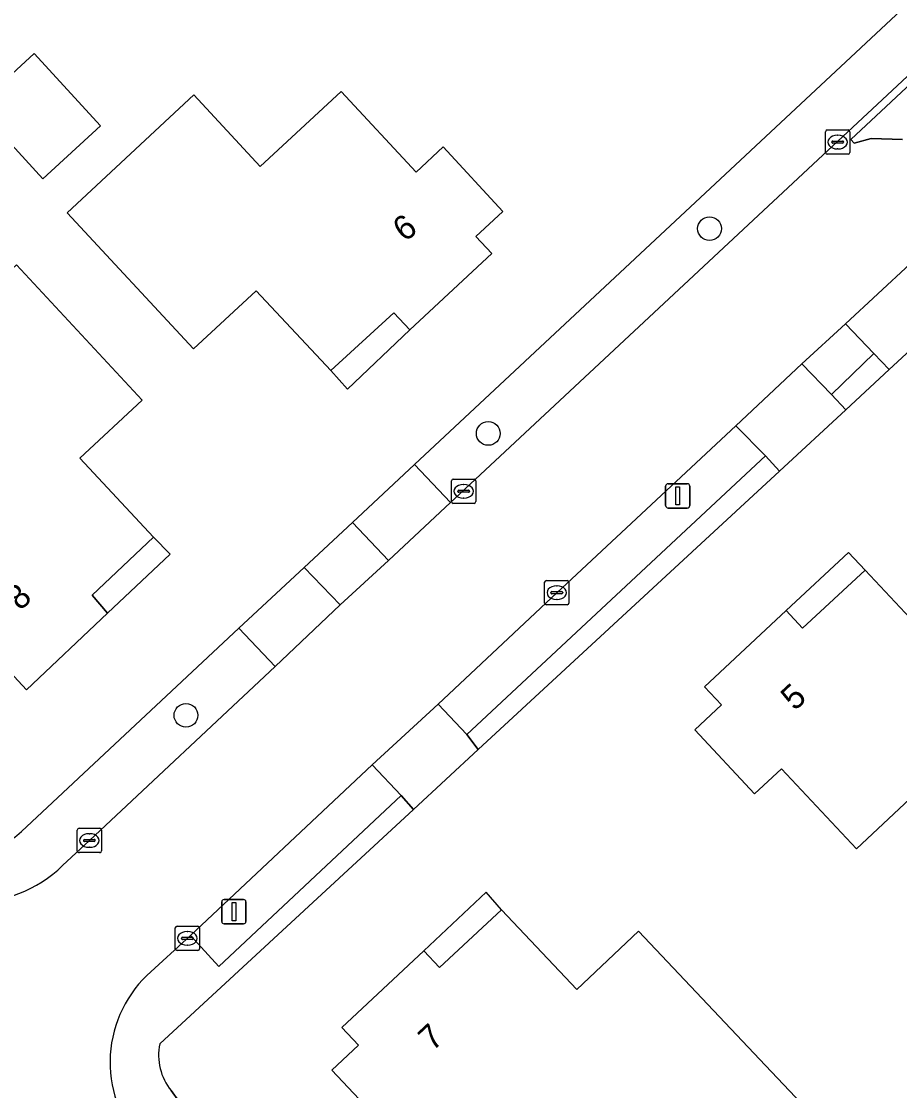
# Model space of a CAD drawing. Extents: x 162661 to 163484, y 380247 to 381230.
# Drawn here: x 163330.1 to 163366.19, y 380849.27 to 380893.22 of the extents above; entities that cross this region are included whole.
import ezdxf

# ---------------------------------------------------------------- set-up
doc = ezdxf.new("R2010")
doc.units = 0
for name, color, linetype in [('IMGEO_Berm_groen', 7, 'Continuous'), ('IMGEO_Boom', 7, 'Continuous'), ('IMGEO_Erf', 7, 'Continuous'), ('IMGEO_Groenvoorziening', 7, 'Continuous'), ('IMGEO_Haag', 7, 'Continuous'), ('IMGEO_Kolk', 7, 'Continuous'), ('IMGEO_Lichtmast', 7, 'Continuous'), ('IMGEO_Pand', 7, 'Continuous'), ('IMGEO_Pand_nummerreeks', 7, 'Continuous'), ('IMGEO_Pand_overbouw', 7, 'Continuous'), ('IMGEO_Parkeervlak_halfverhard', 7, 'Continuous'), ('IMGEO_Rijbaan_lokaal_gesloten', 7, 'Continuous'), ('IMGEO_Voetpad_halfverhard', 7, 'Continuous'), ('IMGEO_Voetpad_open', 7, 'Continuous')]:
    doc.layers.add(name, color=color, linetype=linetype)

msp = doc.modelspace()

# ---------------------------------------------------------------- linework, layer by layer
at = {"layer": 'IMGEO_Berm_groen'}
for points in [[(163340.526, 380866.706), (163339.041, 380868.279), (163330.099, 380859.929)], [(163331.793, 380858.522), (163332.894, 380859.553), (163340.526, 380866.706)]]:
    msp.add_lwpolyline(points, dxfattribs=at)
for centre, radius, start, end in [((163327.945, 380862.085), 3.048, 239.5806, 314.9707), ((163328.001, 380862.453), 5.462, 223.9538, 313.9694)]:
    msp.add_arc(centre, radius, start, end, dxfattribs=at)
at = {"layer": 'IMGEO_Boom'}
for centre in [(163358.382, 380884.702), (163349.288, 380876.285), (163336.864, 380864.698)]:
    msp.add_circle(centre, 0.489, dxfattribs=at)
at = {"layer": 'IMGEO_Erf'}
for points in [[(163412.189, 380922.438), (163401.222, 380911.928), (163398.601, 380909.502), (163391.052, 380902.669), (163388.46, 380900.109), (163368.391, 380881.338), (163365.767, 380878.911), (163363.981, 380877.26), (163361.251, 380874.736), (163348.876, 380863.295), (163346.208, 380860.828), (163335.787, 380851.194)], [(163330.099, 380859.929), (163339.041, 380868.279), (163341.718, 380870.779), (163343.701, 380872.63), (163346.254, 380875.013), (163369.133, 380896.376), (163371.715, 380898.787), (163373.061, 380900.044), (163376.845, 380903.636), (163390.208, 380916.036)], [(163336.256, 380849.272), (163336.881, 380848.403), (163338.801, 380846.249), (163364.11, 380819.217)]]:
    msp.add_lwpolyline(points, dxfattribs=at)
for points in [[(163333.348, 380888.927), (163330.977, 380886.75), (163328.248, 380889.724), (163330.619, 380891.9)], [(163346.319, 380887.029), (163347.431, 380888.061), (163349.892, 380885.413), (163348.781, 380884.381), (163349.434, 380883.679), (163346.063, 380880.54), (163345.41, 380881.242), (163342.822, 380878.871), (163339.742, 380882.153), (163337.167, 380879.761), (163331.974, 380885.353), (163337.191, 380890.199), (163339.918, 380887.263), (163343.236, 380890.346)], [(163335.526, 380872.02), (163333.012, 380869.643), (163333.644, 380868.901), (163330.314, 380865.749), (163329.63, 380866.48), (163328.538, 380865.451), (163326.089, 380868.083), (163327.193, 380869.11), (163324.125, 380872.407), (163327.423, 380875.474), (163324.709, 380878.39), (163329.893, 380883.212), (163335.061, 380877.654), (163332.502, 380875.273)], [(163370.437, 380859.384), (163367.707, 380862.295), (163364.418, 380859.211), (163361.334, 380862.5), (163360.233, 380861.468), (163357.771, 380864.095), (163358.873, 380865.128), (163358.173, 380865.876), (163361.528, 380869), (163362.208, 380868.274), (163364.776, 380870.664), (163367.855, 380867.382), (163370.408, 380869.776), (163375.607, 380864.234)], [(163363.882, 380846.918), (163359.74, 380843.055), (163356.584, 380846.44), (163355.528, 380845.443), (163352.791, 380848.343), (163349.513, 380845.249), (163346.419, 380848.527), (163345.322, 380847.491), (163342.852, 380850.109), (163343.953, 380851.135), (163343.269, 380851.862), (163346.634, 380855.024), (163347.281, 380854.326), (163349.833, 380856.699), (163352.921, 380853.428), (163355.466, 380855.831), (163360.682, 380850.307)]]:
    msp.add_lwpolyline(points, close=True, dxfattribs=at)
for centre, radius, start, end in [((163327.945, 380862.085), 3.048, 239.5806, 314.9707), ((163338.036, 380850.725), 2.297, 168.2096, 219.2166)]:
    msp.add_arc(centre, radius, start, end, dxfattribs=at)
at = {"layer": 'IMGEO_Groenvoorziening'}
for points in [[(163369.133, 380896.376), (163346.254, 380875.013), (163347.737, 380873.443), (163370.584, 380894.778)], [(163363.39, 380877.885), (163363.981, 380877.26), (163365.767, 380878.911), (163365.131, 380879.565)], [(163360.677, 380875.363), (163348.4, 380863.91), (163348.876, 380863.295), (163361.251, 380874.736)], [(163343.204, 380869.236), (163345.186, 380871.061), (163343.701, 380872.63), (163341.718, 380870.779)]]:
    msp.add_lwpolyline(points, close=True, dxfattribs=at)
for points in [[(163369.075, 380891.078), (163369.074, 380892.193), (163369.322, 380892.879), (163369.165, 380893.006), (163364.183, 380888.363), (163364.325, 380888.214), (163365.021, 380888.414), (163366.314, 380888.368)], [(163335.787, 380851.194), (163346.208, 380860.828), (163345.701, 380861.401), (163338.217, 380854.377), (163337.045, 380855.644), (163335.253, 380854.006)], [(163364.11, 380819.217), (163338.801, 380846.249), (163336.881, 380848.403), (163336.256, 380849.272)]]:
    msp.add_lwpolyline(points, dxfattribs=at)
for centre, radius, start, end in [((163338.712, 380850.437), 4.97, 134.1, 224.5357), ((163338.036, 380850.725), 2.297, 168.2096, 219.2166)]:
    msp.add_arc(centre, radius, start, end, dxfattribs=at)
at = {"layer": 'IMGEO_Haag'}
for points in [[(163363.39, 380877.885), (163363.981, 380877.26), (163365.767, 380878.911), (163365.131, 380879.565)], [(163360.677, 380875.363), (163348.4, 380863.91), (163348.876, 380863.295), (163361.251, 380874.736)]]:
    msp.add_lwpolyline(points, close=True, dxfattribs=at)
at = {"layer": 'IMGEO_Kolk'}
for p, q in [((163363.221, 380888.759), (163364.073, 380888.759)), ((163363.146, 380887.833), (163363.146, 380888.685)), ((163363.448, 380888.302), (163363.846, 380888.302)), ((163363.634, 380888.539), (163363.659, 380888.539)), ((163364.147, 380888.685), (163364.147, 380887.833)), ((163363.405, 380888.253), (163363.405, 380888.265)), ((163363.843, 380888.216), (163363.445, 380888.216)), ((163363.657, 380887.979), (163363.632, 380887.979)), ((163363.889, 380888.265), (163363.889, 380888.253)), ((163364.073, 380887.759), (163363.221, 380887.759)), ((163347.775, 380873.482), (163347.775, 380874.334)), ((163347.85, 380874.408), (163348.702, 380874.408)), ((163348.776, 380874.334), (163348.776, 380873.482)), ((163348.034, 380873.902), (163348.034, 380873.914)), ((163348.472, 380873.865), (163348.074, 380873.865)), ((163348.077, 380873.951), (163348.475, 380873.951)), ((163348.263, 380874.188), (163348.288, 380874.188)), ((163348.518, 380873.914), (163348.518, 380873.902)), ((163348.702, 380873.408), (163347.85, 380873.408)), ((163348.286, 380873.628), (163348.261, 380873.628)), ((163351.603, 380869.313), (163351.603, 380870.165)), ((163351.678, 380870.239), (163352.53, 380870.239)), ((163352.091, 380870.019), (163352.116, 380870.019)), ((163352.604, 380870.165), (163352.604, 380869.313)), ((163351.862, 380869.733), (163351.862, 380869.745)), ((163352.3, 380869.696), (163351.902, 380869.696)), ((163351.905, 380869.782), (163352.303, 380869.782)), ((163352.114, 380869.459), (163352.089, 380869.459)), ((163352.346, 380869.745), (163352.346, 380869.733)), ((163352.53, 380869.239), (163351.678, 380869.239)), ((163332.393, 380859.127), (163332.393, 380859.979)), ((163332.468, 380860.053), (163333.32, 380860.053)), ((163332.881, 380859.833), (163332.906, 380859.833)), ((163333.394, 380859.979), (163333.394, 380859.127)), ((163332.652, 380859.547), (163332.652, 380859.559)), ((163333.09, 380859.51), (163332.692, 380859.51)), ((163332.695, 380859.596), (163333.093, 380859.596)), ((163332.904, 380859.273), (163332.879, 380859.273)), ((163333.136, 380859.559), (163333.136, 380859.547)), ((163333.32, 380859.053), (163332.468, 380859.053)), ((163336.421, 380855.105), (163336.421, 380855.957)), ((163336.496, 380856.031), (163337.348, 380856.031)), ((163336.909, 380855.811), (163336.934, 380855.811)), ((163337.422, 380855.957), (163337.422, 380855.105)), ((163336.68, 380855.525), (163336.68, 380855.537)), ((163337.118, 380855.488), (163336.72, 380855.488)), ((163336.723, 380855.574), (163337.121, 380855.574)), ((163337.164, 380855.537), (163337.164, 380855.525)), ((163337.348, 380855.031), (163336.496, 380855.031)), ((163336.932, 380855.251), (163336.907, 380855.251))]:
    msp.add_line(p, q, dxfattribs=at)
for points in [[(163363.221, 380888.759), (163364.073, 380888.759)], [(163363.146, 380887.833), (163363.146, 380888.685)], [(163364.147, 380888.685), (163364.147, 380887.833)], [(163364.073, 380887.759), (163363.221, 380887.759)], [(163347.775, 380873.482), (163347.775, 380874.334)], [(163347.85, 380874.408), (163348.702, 380874.408)], [(163348.776, 380874.334), (163348.776, 380873.482)], [(163348.702, 380873.408), (163347.85, 380873.408)], [(163351.603, 380869.313), (163351.603, 380870.165)], [(163351.678, 380870.239), (163352.53, 380870.239)], [(163352.604, 380870.165), (163352.604, 380869.313)], [(163352.53, 380869.239), (163351.678, 380869.239)], [(163332.393, 380859.127), (163332.393, 380859.979)], [(163332.468, 380860.053), (163333.32, 380860.053)], [(163333.394, 380859.979), (163333.394, 380859.127)], [(163333.32, 380859.053), (163332.468, 380859.053)], [(163336.421, 380855.105), (163336.421, 380855.957)], [(163336.496, 380856.031), (163337.348, 380856.031)], [(163337.422, 380855.957), (163337.422, 380855.105)], [(163337.348, 380855.031), (163336.496, 380855.031)]]:
    msp.add_lwpolyline(points, dxfattribs=at)
for centre, radius, start, end in [((163363.223, 380888.683), 0.0765, 91.552, 178.448), ((163363.223, 380888.683), 0.0765, 91.552, 178.448), ((163364.071, 380888.683), 0.0765, 1.552, 88.448), ((163364.071, 380888.683), 0.0765, 1.552, 88.448), ((163363.445, 380888.262), 0.0403, 85.8775, 175.7526), ((163363.85, 380888.264), 0.0386, 1.7309, 96.639), ((163363.442, 380888.252), 0.0366, 178.938, 274.7102), ((163363.846, 380888.259), 0.043, 264.8664, 352.4533), ((163363.223, 380887.835), 0.0765, 181.552, 268.448), ((163363.223, 380887.835), 0.0765, 181.552, 268.448), ((163364.071, 380887.835), 0.0765, 271.552, 358.448), ((163364.071, 380887.835), 0.0765, 271.552, 358.448), ((163347.852, 380874.332), 0.0765, 91.552, 178.448), ((163347.852, 380874.332), 0.0765, 91.552, 178.448), ((163348.7, 380874.332), 0.0765, 1.552, 88.448), ((163348.7, 380874.332), 0.0765, 1.552, 88.448), ((163348.074, 380873.911), 0.0403, 85.8775, 175.7526), ((163348.071, 380873.901), 0.0366, 178.938, 274.7102), ((163348.475, 380873.908), 0.043, 264.8664, 352.4533), ((163348.479, 380873.913), 0.0386, 1.7309, 96.639), ((163347.852, 380873.484), 0.0765, 181.552, 268.448), ((163347.852, 380873.484), 0.0765, 181.552, 268.448), ((163348.7, 380873.484), 0.0765, 271.552, 358.448), ((163348.7, 380873.484), 0.0765, 271.552, 358.448), ((163351.68, 380870.163), 0.0765, 91.552, 178.448), ((163351.68, 380870.163), 0.0765, 91.552, 178.448), ((163352.528, 380870.163), 0.0765, 1.552, 88.448), ((163352.528, 380870.163), 0.0765, 1.552, 88.448), ((163351.902, 380869.742), 0.0403, 85.8775, 175.7526), ((163351.899, 380869.732), 0.0366, 178.938, 274.7102), ((163352.303, 380869.739), 0.043, 264.8664, 352.4533), ((163352.307, 380869.744), 0.0386, 1.7309, 96.639), ((163351.68, 380869.315), 0.0765, 181.552, 268.448), ((163351.68, 380869.315), 0.0765, 181.552, 268.448), ((163352.528, 380869.315), 0.0765, 271.552, 358.448), ((163352.528, 380869.315), 0.0765, 271.552, 358.448), ((163332.47, 380859.977), 0.0765, 91.552, 178.448), ((163332.47, 380859.977), 0.0765, 91.552, 178.448), ((163333.318, 380859.977), 0.0765, 1.552, 88.448), ((163333.318, 380859.977), 0.0765, 1.552, 88.448), ((163332.692, 380859.556), 0.0403, 85.8775, 175.7526), ((163332.689, 380859.546), 0.0366, 178.938, 274.7102), ((163333.093, 380859.553), 0.043, 264.8664, 352.4533), ((163333.097, 380859.558), 0.0386, 1.7309, 96.639), ((163332.47, 380859.129), 0.0765, 181.552, 268.448), ((163332.47, 380859.129), 0.0765, 181.552, 268.448), ((163333.318, 380859.129), 0.0765, 271.552, 358.448), ((163333.318, 380859.129), 0.0765, 271.552, 358.448), ((163336.498, 380855.955), 0.0765, 91.552, 178.448), ((163336.498, 380855.955), 0.0765, 91.552, 178.448), ((163337.346, 380855.955), 0.0765, 1.552, 88.448), ((163337.346, 380855.955), 0.0765, 1.552, 88.448), ((163336.72, 380855.534), 0.0403, 85.8775, 175.7526), ((163336.717, 380855.524), 0.0366, 178.938, 274.7102), ((163337.121, 380855.531), 0.043, 264.8664, 352.4533), ((163337.125, 380855.536), 0.0386, 1.7309, 96.639), ((163336.498, 380855.107), 0.0765, 181.552, 268.448), ((163336.498, 380855.107), 0.0765, 181.552, 268.448), ((163337.346, 380855.107), 0.0765, 271.552, 358.448), ((163337.346, 380855.107), 0.0765, 271.552, 358.448)]:
    msp.add_arc(centre, radius, start, end, dxfattribs=at)
for centre, major_axis, ratio, start_param, end_param in [((163363.633, 380888.259), (-0.387, 0.002), 0.722429, 4.712389, 7.853982), ((163363.658, 380888.259), (-0.39, 0.002), 0.717154, 1.570796, 4.712389), ((163348.262, 380873.908), (-0.387, 0.002), 0.722429, 4.712389, 7.853982), ((163348.287, 380873.908), (-0.39, 0.002), 0.717154, 1.570796, 4.712389), ((163352.09, 380869.739), (-0.387, 0.002), 0.722429, 4.712389, 7.853982), ((163352.115, 380869.739), (-0.39, 0.002), 0.717154, 1.570796, 4.712389), ((163332.88, 380859.553), (-0.387, 0.002), 0.722429, 4.712389, 7.853982), ((163332.905, 380859.553), (-0.39, 0.002), 0.717154, 1.570796, 4.712389), ((163336.908, 380855.531), (-0.387, 0.002), 0.722429, 4.712389, 7.853982), ((163336.933, 380855.531), (-0.39, 0.002), 0.717154, 1.570796, 4.712389)]:
    msp.add_ellipse(centre, major_axis=major_axis, ratio=ratio, start_param=start_param, end_param=end_param, dxfattribs=at)
at = {"layer": 'IMGEO_Lichtmast'}
for p, q in [((163356.677, 380874.22), (163357.467, 380874.22)), ((163357.467, 380874.22), (163356.677, 380874.22)), ((163356.577, 380873.32), (163356.577, 380874.12)), ((163356.577, 380874.12), (163356.577, 380873.32)), ((163357.567, 380874.12), (163357.567, 380873.32)), ((163357.567, 380873.32), (163357.567, 380874.12)), ((163357.467, 380873.22), (163356.677, 380873.22)), ((163356.677, 380873.22), (163357.467, 380873.22)), ((163338.436, 380857.128), (163339.226, 380857.128)), ((163339.226, 380857.128), (163338.436, 380857.128)), ((163338.336, 380856.228), (163338.336, 380857.028)), ((163338.336, 380857.028), (163338.336, 380856.228)), ((163339.326, 380857.028), (163339.326, 380856.228)), ((163339.326, 380856.228), (163339.326, 380857.028)), ((163339.226, 380856.128), (163338.436, 380856.128)), ((163338.436, 380856.128), (163339.226, 380856.128))]:
    msp.add_line(p, q, dxfattribs=at)
for points in [[(163356.997, 380874.095), (163357.147, 380874.095), (163357.147, 380873.345), (163356.997, 380873.345), (163356.997, 380874.095)], [(163338.756, 380857.003), (163338.906, 380857.003), (163338.906, 380856.253), (163338.756, 380856.253), (163338.756, 380857.003)]]:
    msp.add_lwpolyline(points, dxfattribs=at)
for centre, start, end in [((163356.677, 380874.12), 90, 180), ((163356.677, 380874.12), 90, 180), ((163357.467, 380874.12), 0, 90), ((163357.467, 380874.12), 360, 90), ((163356.677, 380873.32), 180, 270), ((163356.677, 380873.32), 180, 270), ((163357.467, 380873.32), 270, 0), ((163357.467, 380873.32), 270, 0), ((163338.436, 380857.028), 90, 180), ((163338.436, 380857.028), 90, 180), ((163339.226, 380857.028), 0, 90), ((163339.226, 380857.028), 360, 90), ((163338.436, 380856.228), 180, 270), ((163338.436, 380856.228), 180, 270), ((163339.226, 380856.228), 270, 0), ((163339.226, 380856.228), 270, 0)]:
    msp.add_arc(centre, 0.1, start, end, dxfattribs=at)
at = {"layer": 'IMGEO_Pand'}
for points in [[(163330.619, 380891.9), (163328.248, 380889.724), (163330.977, 380886.75), (163333.348, 380888.927)], [(163337.167, 380879.761), (163339.742, 380882.153), (163342.822, 380878.871), (163345.41, 380881.242), (163346.063, 380880.54), (163349.434, 380883.679), (163348.781, 380884.381), (163349.892, 380885.413), (163347.431, 380888.061), (163346.319, 380887.029), (163343.236, 380890.346), (163339.918, 380887.263), (163337.191, 380890.199), (163331.974, 380885.353)], [(163335.526, 380872.02), (163332.502, 380875.273), (163335.061, 380877.654), (163329.893, 380883.212), (163324.709, 380878.39), (163327.423, 380875.474), (163324.125, 380872.407), (163327.193, 380869.11), (163326.089, 380868.083), (163328.538, 380865.451), (163329.63, 380866.48), (163330.314, 380865.749), (163333.644, 380868.901), (163333.012, 380869.643)], [(163361.528, 380869), (163358.173, 380865.876), (163358.873, 380865.128), (163357.771, 380864.095), (163360.233, 380861.468), (163361.334, 380862.5), (163364.418, 380859.211), (163367.707, 380862.295), (163370.437, 380859.384), (163375.607, 380864.234), (163370.408, 380869.776), (163367.855, 380867.382), (163364.776, 380870.664), (163362.208, 380868.274)], [(163355.466, 380855.831), (163352.921, 380853.428), (163349.833, 380856.699), (163347.281, 380854.326), (163346.634, 380855.024), (163343.269, 380851.862), (163343.953, 380851.135), (163342.852, 380850.109), (163345.322, 380847.491), (163346.419, 380848.527), (163349.513, 380845.249), (163352.791, 380848.343), (163355.528, 380845.443), (163356.584, 380846.44), (163359.74, 380843.055), (163363.882, 380846.918), (163360.682, 380850.307)]]:
    msp.add_lwpolyline(points, close=True, dxfattribs=at)
at = {"layer": 'IMGEO_Pand_overbouw'}
for points in [[(163346.063, 380880.54), (163345.41, 380881.242), (163342.822, 380878.871), (163343.501, 380878.107)], [(163335.526, 380872.02), (163333.012, 380869.643), (163333.644, 380868.901), (163336.207, 380871.326)], [(163361.528, 380869), (163362.208, 380868.274), (163364.776, 380870.664), (163364.095, 380871.391)], [(163346.634, 380855.024), (163347.281, 380854.326), (163349.833, 380856.699), (163349.196, 380857.435)]]:
    msp.add_lwpolyline(points, close=True, dxfattribs=at)
at = {"layer": 'IMGEO_Parkeervlak_halfverhard'}
for points in [[(163360.677, 380875.363), (163359.467, 380876.598), (163352.104, 380869.739), (163347.222, 380865.158), (163348.4, 380863.91)], [(163345.701, 380861.401), (163344.52, 380862.667), (163337.045, 380855.644), (163338.217, 380854.377)]]:
    msp.add_lwpolyline(points, close=True, dxfattribs=at)
at = {"layer": 'IMGEO_Rijbaan_lokaal_gesloten'}
for points in [[(163370.584, 380894.778), (163347.737, 380873.443), (163345.186, 380871.061), (163343.204, 380869.236), (163340.526, 380866.706), (163332.894, 380859.553), (163331.793, 380858.522)], [(163366.314, 380888.368), (163365.021, 380888.414), (163364.325, 380888.214), (163364.183, 380888.363), (163369.165, 380893.006), (163369.322, 380892.879), (163369.074, 380892.193), (163369.075, 380891.078)], [(163352.104, 380869.739), (163359.467, 380876.598), (163362.17, 380879.145), (163363.968, 380880.786), (163366.621, 380883.251)], [(163335.253, 380854.006), (163337.045, 380855.644), (163344.52, 380862.667), (163347.222, 380865.158), (163352.104, 380869.739)]]:
    msp.add_lwpolyline(points, dxfattribs=at)
for centre, radius, start, end in [((163328.001, 380862.453), 5.462, 223.9538, 313.9694), ((163338.712, 380850.437), 4.97, 134.1, 224.5357)]:
    msp.add_arc(centre, radius, start, end, dxfattribs=at)
at = {"layer": 'IMGEO_Voetpad_halfverhard'}
msp.add_lwpolyline([(163365.131, 380879.565), (163363.968, 380880.786), (163362.17, 380879.145), (163363.39, 380877.885)], close=True, dxfattribs=at)
at = {"layer": 'IMGEO_Voetpad_open'}
for points in [[(163366.621, 380883.251), (163363.968, 380880.786), (163365.131, 380879.565), (163365.767, 380878.911), (163368.391, 380881.338), (163367.834, 380881.918)], [(163363.39, 380877.885), (163362.17, 380879.145), (163359.467, 380876.598), (163360.677, 380875.363), (163361.251, 380874.736), (163363.981, 380877.26)], [(163347.737, 380873.443), (163346.254, 380875.013), (163343.701, 380872.63), (163345.186, 380871.061)], [(163339.041, 380868.279), (163340.526, 380866.706), (163343.204, 380869.236), (163341.718, 380870.779)], [(163347.222, 380865.158), (163344.52, 380862.667), (163345.701, 380861.401), (163346.208, 380860.828), (163348.876, 380863.295), (163348.4, 380863.91)]]:
    msp.add_lwpolyline(points, close=True, dxfattribs=at)

# ---------------------------------------------------------------- texts
at = {"layer": 'IMGEO_Pand_nummerreeks'}
for s, rotation, p in [('6', 37.0212, (163345.848, 380884.131)), ('8', 43.426, (163330.049, 380868.968)), ('5', 42.9625, (163361.885, 380864.851)), ('7', 43.2182, (163346.996, 380850.863))]:
    msp.add_text(s, height=1, rotation=rotation, dxfattribs=at).set_placement(p)

doc.saveas('drawing.dxf')
